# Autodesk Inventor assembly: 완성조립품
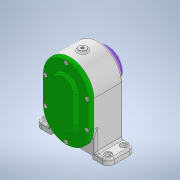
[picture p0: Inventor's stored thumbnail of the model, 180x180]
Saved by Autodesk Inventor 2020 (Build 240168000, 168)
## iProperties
Created: 2021-05
Part Number: 완성조립품
Document SubType Name: Assembly
Designer: Owner
Author: Owner
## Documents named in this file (17)
- C:\Users\Owner\Desktop\710507V1013\답안조립품.iam
- C:\Users\Owner\Desktop\710507V1013\1-본체.ipt
- C:\Users\Owner\Desktop\710507V1013\베어링 6001.ipt
- 베어링 6001.ipt
- C:\Users\Owner\Desktop\710507V1013\축 A.ipt
- C:\Users\Owner\Desktop\710507V1013\축 B.ipt
- C:\Users\Owner\Desktop\710507V1013\키 5 x 5 x 12.ipt
- C:\Users\Owner\Desktop\710507V1013\키 4 x 4 x 12.ipt
- C:\Users\Owner\Desktop\710507V1013\칼라.ipt
- C:\Users\Owner\Desktop\710507V1013\커버 A.ipt
- C:\Users\Owner\Desktop\710507V1013\베어링 6002.ipt
- 베어링 6002.ipt
- C:\Users\Owner\Desktop\710507V1013\커버 B.ipt
- C:\Users\Owner\Desktop\710507V1013\오일 실 12 22 7.ipt
- C:\Users\Owner\Desktop\710507V1013\볼트 M4.ipt
- C:\Users\Owner\Desktop\710507V1013\스퍼기어 A.ipt
- C:\Users\Owner\Desktop\710507V1013\스퍼기어 B.ipt
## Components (1 placed, 1 different names)
1. 1-본체:1
